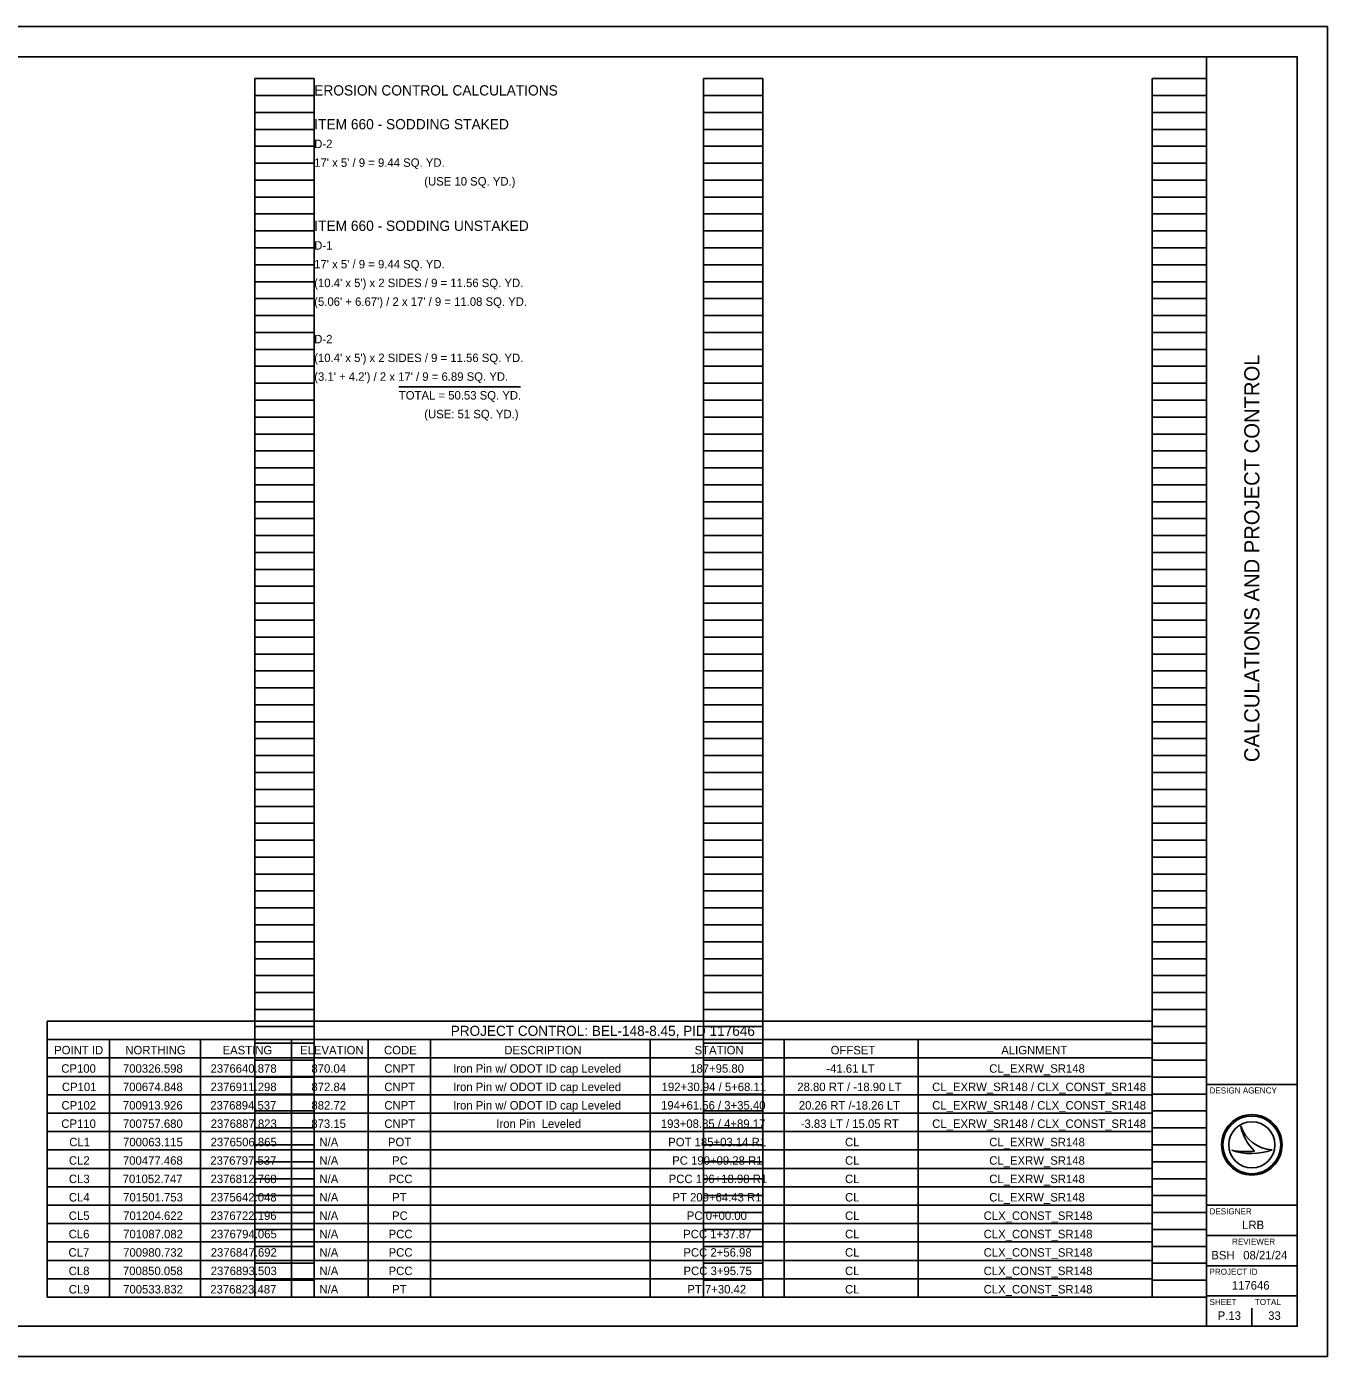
# Model space of a CAD drawing. Extents: x 0 to 34, y 0 to 22.
# Drawn here: x 12.48 to 34, y 0 to 22 of the extents above; entities that cross this region are included whole.
import ezdxf

# ---------------------------------------------------------------- set-up
doc = ezdxf.new("R2010")
doc.units = 0
for name, color, linetype in [('SH_Border', 7, 'Continuous'), ('SH_Cut_Line', 7, 'Continuous'), ('SH_Data', 7, 'Continuous'), ('SH_Text', 7, 'Continuous')]:
    doc.layers.add(name, color=color, linetype=linetype)

msp = doc.modelspace()

# ---------------------------------------------------------------- linework, layer by layer
at = {"layer": 'SH_Border'}
for p, q in [((32, 0.5), (32, 21.5)), ((32, 4.5), (33.5, 4.5)), ((32, 2.5), (33.5, 2.5)), ((32, 2), (33.5, 2)), ((32, 1.5), (33.5, 1.5)), ((32, 1), (33.5, 1))]:
    msp.add_line(p, q, dxfattribs=at)
msp.add_lwpolyline([(1.5, 21.5), (33.5, 21.5), (33.5, 0.5), (1.5, 0.5)], close=True, dxfattribs=at)
at = {"layer": 'SH_Cut_Line'}
msp.add_lwpolyline([(0, 0), (34, 0), (34, 22), (0, 22)], close=True, dxfattribs=at)
at = {"layer": 'SH_Data'}
for p, q in [((16.26, 0.98), (16.26, 21.14)), ((16.26, 21.14), (17.24, 21.14)), ((17.24, 0.98), (17.24, 21.14)), ((23.68, 0.98), (23.68, 21.14)), ((23.68, 21.14), (24.66, 21.14)), ((24.66, 0.98), (24.66, 21.14)), ((31.1, 0.98), (31.1, 21.14)), ((31.1, 21.14), (32, 21.14)), ((32, 0.98), (32, 21.14)), ((16.26, 20.86), (17.24, 20.86)), ((23.68, 20.86), (24.66, 20.86)), ((31.1, 20.86), (32, 20.86)), ((16.26, 20.58), (17.24, 20.58)), ((23.68, 20.58), (24.66, 20.58)), ((31.1, 20.58), (32, 20.58)), ((16.26, 20.3), (17.24, 20.3)), ((23.68, 20.3), (24.66, 20.3)), ((31.1, 20.3), (32, 20.3)), ((16.26, 20.02), (17.24, 20.02)), ((23.68, 20.02), (24.66, 20.02)), ((31.1, 20.02), (32, 20.02)), ((16.26, 19.74), (17.24, 19.74)), ((23.68, 19.74), (24.66, 19.74)), ((31.1, 19.74), (32, 19.74)), ((16.26, 19.46), (17.24, 19.46)), ((23.68, 19.46), (24.66, 19.46)), ((31.1, 19.46), (32, 19.46)), ((16.26, 19.18), (17.24, 19.18)), ((23.68, 19.18), (24.66, 19.18)), ((31.1, 19.18), (32, 19.18)), ((16.26, 18.9), (17.24, 18.9)), ((23.68, 18.9), (24.66, 18.9)), ((31.1, 18.9), (32, 18.9)), ((16.26, 18.62), (17.24, 18.62)), ((23.68, 18.62), (24.66, 18.62)), ((31.1, 18.62), (32, 18.62)), ((16.26, 18.34), (17.24, 18.34)), ((23.68, 18.34), (24.66, 18.34)), ((31.1, 18.34), (32, 18.34)), ((16.26, 18.06), (17.24, 18.06)), ((23.68, 18.06), (24.66, 18.06)), ((31.1, 18.06), (32, 18.06)), ((16.26, 17.78), (17.24, 17.78)), ((23.68, 17.78), (24.66, 17.78)), ((31.1, 17.78), (32, 17.78)), ((16.26, 17.5), (17.24, 17.5)), ((23.68, 17.5), (24.66, 17.5)), ((31.1, 17.5), (32, 17.5)), ((16.26, 17.22), (17.24, 17.22)), ((23.68, 17.22), (24.66, 17.22)), ((31.1, 17.22), (32, 17.22)), ((16.26, 16.94), (17.24, 16.94)), ((23.68, 16.94), (24.66, 16.94)), ((31.1, 16.94), (32, 16.94)), ((16.26, 16.66), (17.24, 16.66)), ((23.68, 16.66), (24.66, 16.66)), ((31.1, 16.66), (32, 16.66)), ((16.26, 16.38), (17.24, 16.38)), ((23.68, 16.38), (24.66, 16.38)), ((31.1, 16.38), (32, 16.38)), ((16.26, 16.1), (17.24, 16.1)), ((23.68, 16.1), (24.66, 16.1)), ((31.1, 16.1), (32, 16.1)), ((16.26, 15.82), (17.24, 15.82)), ((23.68, 15.82), (24.66, 15.82)), ((31.1, 15.82), (32, 15.82)), ((16.26, 15.54), (17.24, 15.54)), ((23.68, 15.54), (24.66, 15.54)), ((31.1, 15.54), (32, 15.54)), ((16.26, 15.26), (17.24, 15.26)), ((23.68, 15.26), (24.66, 15.26)), ((31.1, 15.26), (32, 15.26)), ((16.26, 14.98), (17.24, 14.98)), ((23.68, 14.98), (24.66, 14.98)), ((31.1, 14.98), (32, 14.98)), ((16.26, 14.7), (17.24, 14.7)), ((23.68, 14.7), (24.66, 14.7)), ((31.1, 14.7), (32, 14.7)), ((16.26, 14.42), (17.24, 14.42)), ((23.68, 14.42), (24.66, 14.42)), ((31.1, 14.42), (32, 14.42)), ((16.26, 14.14), (17.24, 14.14)), ((23.68, 14.14), (24.66, 14.14)), ((31.1, 14.14), (32, 14.14)), ((16.26, 13.86), (17.24, 13.86)), ((23.68, 13.86), (24.66, 13.86)), ((31.1, 13.86), (32, 13.86)), ((16.26, 13.58), (17.24, 13.58)), ((23.68, 13.58), (24.66, 13.58)), ((31.1, 13.58), (32, 13.58)), ((16.26, 13.3), (17.24, 13.3)), ((23.68, 13.3), (24.66, 13.3)), ((31.1, 13.3), (32, 13.3)), ((16.26, 13.02), (17.24, 13.02)), ((23.68, 13.02), (24.66, 13.02)), ((31.1, 13.02), (32, 13.02)), ((16.26, 12.74), (17.24, 12.74)), ((23.68, 12.74), (24.66, 12.74)), ((31.1, 12.74), (32, 12.74)), ((16.26, 12.46), (17.24, 12.46)), ((23.68, 12.46), (24.66, 12.46)), ((31.1, 12.46), (32, 12.46)), ((16.26, 12.18), (17.24, 12.18)), ((23.68, 12.18), (24.66, 12.18)), ((31.1, 12.18), (32, 12.18)), ((16.26, 11.9), (17.24, 11.9)), ((23.68, 11.9), (24.66, 11.9)), ((31.1, 11.9), (32, 11.9)), ((16.26, 11.62), (17.24, 11.62)), ((23.68, 11.62), (24.66, 11.62)), ((31.1, 11.62), (32, 11.62)), ((16.26, 11.34), (17.24, 11.34)), ((23.68, 11.34), (24.66, 11.34)), ((31.1, 11.34), (32, 11.34)), ((16.26, 11.06), (17.24, 11.06)), ((23.68, 11.06), (24.66, 11.06)), ((31.1, 11.06), (32, 11.06)), ((16.26, 10.78), (17.24, 10.78)), ((23.68, 10.78), (24.66, 10.78)), ((31.1, 10.78), (32, 10.78)), ((16.26, 10.5), (17.24, 10.5)), ((23.68, 10.5), (24.66, 10.5)), ((31.1, 10.5), (32, 10.5)), ((16.26, 10.22), (17.24, 10.22)), ((23.68, 10.22), (24.66, 10.22)), ((31.1, 10.22), (32, 10.22)), ((16.26, 9.94), (17.24, 9.94)), ((23.68, 9.94), (24.66, 9.94)), ((31.1, 9.94), (32, 9.94)), ((16.26, 9.66), (17.24, 9.66)), ((23.68, 9.66), (24.66, 9.66)), ((31.1, 9.66), (32, 9.66)), ((16.26, 9.38), (17.24, 9.38)), ((23.68, 9.38), (24.66, 9.38)), ((31.1, 9.38), (32, 9.38)), ((16.26, 9.1), (17.24, 9.1)), ((23.68, 9.1), (24.66, 9.1)), ((31.1, 9.1), (32, 9.1)), ((16.26, 8.82), (17.24, 8.82)), ((23.68, 8.82), (24.66, 8.82)), ((31.1, 8.82), (32, 8.82)), ((16.26, 8.54), (17.24, 8.54)), ((23.68, 8.54), (24.66, 8.54)), ((31.1, 8.54), (32, 8.54)), ((16.26, 8.26), (17.24, 8.26)), ((23.68, 8.26), (24.66, 8.26)), ((31.1, 8.26), (32, 8.26)), ((16.26, 7.98), (17.24, 7.98)), ((23.68, 7.98), (24.66, 7.98)), ((31.1, 7.98), (32, 7.98)), ((16.26, 7.7), (17.24, 7.7)), ((23.68, 7.7), (24.66, 7.7)), ((31.1, 7.7), (32, 7.7)), ((16.26, 7.42), (17.24, 7.42)), ((23.68, 7.42), (24.66, 7.42)), ((31.1, 7.42), (32, 7.42)), ((16.26, 7.14), (17.24, 7.14)), ((23.68, 7.14), (24.66, 7.14)), ((31.1, 7.14), (32, 7.14)), ((16.26, 6.86), (17.24, 6.86)), ((23.68, 6.86), (24.66, 6.86)), ((31.1, 6.86), (32, 6.86)), ((16.26, 6.58), (17.24, 6.58)), ((23.68, 6.58), (24.66, 6.58)), ((31.1, 6.58), (32, 6.58)), ((16.26, 6.3), (17.24, 6.3)), ((23.68, 6.3), (24.66, 6.3)), ((31.1, 6.3), (32, 6.3)), ((16.26, 6.02), (17.24, 6.02)), ((23.68, 6.02), (24.66, 6.02)), ((31.1, 6.02), (32, 6.02)), ((16.26, 5.74), (17.24, 5.74)), ((23.68, 5.74), (24.66, 5.74)), ((31.1, 5.74), (32, 5.74)), ((16.26, 5.46), (17.24, 5.46)), ((23.68, 5.46), (24.66, 5.46)), ((31.1, 5.46), (32, 5.46)), ((16.26, 5.18), (17.24, 5.18)), ((23.68, 5.18), (24.66, 5.18)), ((31.1, 5.18), (32, 5.18)), ((16.26, 4.9), (17.24, 4.9)), ((23.68, 4.9), (24.66, 4.9)), ((31.1, 4.9), (32, 4.9)), ((16.26, 4.62), (17.24, 4.62)), ((23.68, 4.62), (24.66, 4.62)), ((31.1, 4.62), (32, 4.62)), ((16.26, 4.34), (17.24, 4.34)), ((23.68, 4.34), (24.66, 4.34)), ((31.1, 4.34), (32, 4.34)), ((16.26, 4.06), (17.24, 4.06)), ((23.68, 4.06), (24.66, 4.06)), ((31.1, 4.06), (32, 4.06)), ((16.26, 3.78), (17.24, 3.78)), ((23.68, 3.78), (24.66, 3.78)), ((31.1, 3.78), (32, 3.78)), ((32.567, 3.81), (32.567, 3.81)), ((16.26, 3.5), (17.24, 3.5)), ((23.68, 3.5), (24.66, 3.5)), ((31.1, 3.5), (32, 3.5)), ((32.417, 3.41), (32.417, 3.41)), ((32.75, 3.5), (32.75, 3.5)), ((33.087, 3.419), (33.087, 3.419)), ((16.26, 3.22), (17.24, 3.22)), ((23.68, 3.22), (24.66, 3.22)), ((31.1, 3.22), (32, 3.22)), ((16.26, 2.94), (17.24, 2.94)), ((23.68, 2.94), (24.66, 2.94)), ((31.1, 2.94), (32, 2.94)), ((16.26, 2.66), (17.24, 2.66)), ((23.68, 2.66), (24.66, 2.66)), ((31.1, 2.66), (32, 2.66)), ((16.26, 2.38), (17.24, 2.38)), ((23.68, 2.38), (24.66, 2.38)), ((31.1, 2.38), (32, 2.38)), ((16.26, 2.1), (17.24, 2.1)), ((23.68, 2.1), (24.66, 2.1)), ((31.1, 2.1), (32, 2.1)), ((16.26, 1.82), (17.24, 1.82)), ((23.68, 1.82), (24.66, 1.82)), ((31.1, 1.82), (32, 1.82)), ((16.26, 1.54), (17.24, 1.54)), ((23.68, 1.54), (24.66, 1.54)), ((31.1, 1.54), (32, 1.54)), ((16.26, 1.26), (17.24, 1.26)), ((23.68, 1.26), (24.66, 1.26)), ((31.1, 1.26), (32, 1.26)), ((16.26, 0.98), (17.24, 0.98)), ((23.68, 0.98), (24.66, 0.98)), ((31.1, 0.98), (32, 0.98)), ((32.375, 0.675), (32.375, 0.675)), ((32.75, 0.5), (32.75, 0.8))]:
    msp.add_line(p, q, dxfattribs=at)
for radius in [0.5, 0.477, 0.477, 0.382]:
    msp.add_circle((32.75, 3.5), radius, dxfattribs=at)
for centre, radius, start, end in [((33.116, 3.998), 0.58, 198.9257, 198.9319), ((33.347, 3.97), 0.796, 191.6379, 191.6421), ((33.116, 3.998), 0.58, 198.9319, 267.1657), ((33.347, 3.97), 0.796, 191.6421, 226.0947), ((32.739, 4.37), 1.013, 251.4576, 290.0832), ((32.648, 4.654), 1.266, 259.4964, 259.4995), ((32.739, 4.37), 1.013, 251.4527, 251.4576), ((32.648, 4.654), 1.266, 259.4995, 276.6672)]:
    msp.add_arc(centre, radius, start, end, dxfattribs=at)
at = {"layer": 'SH_Text'}
for p, q in [((18.64, 16.039), (20.655, 16.039)), ((12.822, 5.545), (31.1, 5.545)), ((12.822, 5.545), (12.822, 0.98)), ((31.1, 5.545), (31.1, 0.98)), ((12.822, 5.241), (31.1, 5.241)), ((13.854, 5.241), (13.854, 4.937)), ((15.358, 5.241), (15.358, 4.937)), ((16.863, 5.241), (16.863, 4.937)), ((18.131, 5.241), (18.131, 4.937)), ((19.163, 5.241), (19.163, 4.937)), ((22.798, 5.241), (22.798, 4.937)), ((25.013, 5.241), (25.013, 4.937)), ((27.228, 5.241), (27.228, 4.937)), ((12.822, 4.937), (31.1, 4.937)), ((13.854, 4.937), (13.854, 0.98)), ((15.358, 4.937), (15.358, 0.98)), ((16.863, 4.937), (16.863, 0.98)), ((18.131, 4.937), (18.131, 0.98)), ((19.163, 4.937), (19.163, 0.98)), ((22.798, 4.937), (22.798, 0.98)), ((25.013, 4.937), (25.013, 0.98)), ((27.228, 4.937), (27.228, 0.98)), ((12.822, 4.632), (31.1, 4.632)), ((12.822, 4.328), (31.1, 4.328)), ((12.822, 4.023), (31.1, 4.023)), ((12.822, 3.719), (31.1, 3.719)), ((12.822, 3.415), (31.1, 3.415)), ((12.822, 3.11), (31.1, 3.11)), ((12.822, 2.806), (31.1, 2.806)), ((12.822, 2.502), (31.1, 2.502)), ((12.822, 2.197), (31.1, 2.197)), ((12.822, 1.893), (31.1, 1.893)), ((12.822, 1.589), (31.1, 1.589)), ((12.822, 1.284), (31.1, 1.284)), ((12.822, 0.98), (31.1, 0.98))]:
    msp.add_line(p, q, dxfattribs=at)

# ---------------------------------------------------------------- texts
at = {"layer": 'SH_Data'}
msp.add_text('CALCULATIONS AND PROJECT CONTROL', height=0.25, rotation=90, dxfattribs=at).set_placement((32.875, 9.832))
for s, height, p in [('DESIGN AGENCY', 0.1, (32.05, 4.35)), ('DESIGNER', 0.1, (32.05, 2.35)), ('LRB', 0.14, (32.589, 2.105)), ('REVIEWER', 0.1, (32.422, 1.85)), ('BSH', 0.14, (32.08, 1.605)), ('08/21/24', 0.14, (32.608, 1.605)), ('PROJECT ID', 0.1, (32.05, 1.35)), ('117646', 0.14, (32.419, 1.105)), ('SHEET', 0.1, (32.05, 0.85)), ('TOTAL', 0.1, (32.8, 0.85)), ('P.13', 0.14, (32.185, 0.605)), ('33', 0.14, (33.02, 0.605))]:
    msp.add_text(s, height=height, dxfattribs=at).set_placement(p)
at = {"layer": 'SH_Text'}
for s, height, p in [('EROSION CONTROL CALCULATIONS', 0.17, (17.24, 20.86)), ('ITEM 660 - SODDING STAKED', 0.17, (17.24, 20.3)), ('D-2', 0.14, (17.24, 19.99)), ("17' x 5' / 9 = 9.44 SQ. YD.", 0.14, (17.24, 19.68)), ('(USE 10 SQ. YD.)', 0.14, (19.06, 19.37)), ('ITEM 660 - SODDING UNSTAKED', 0.17, (17.24, 18.62)), ('D-1', 0.14, (17.24, 18.31)), ("17' x 5' / 9 = 9.44 SQ. YD. ", 0.14, (17.24, 18)), ("(10.4' x 5') x 2 SIDES / 9 = 11.56 SQ. YD. ", 0.14, (17.24, 17.69)), ("(5.06' + 6.67') / 2 x 17' / 9 = 11.08 SQ. YD. ", 0.14, (17.24, 17.38)), ('D-2 ', 0.14, (17.24, 16.76)), ("(10.4' x 5') x 2 SIDES / 9 = 11.56 SQ. YD. ", 0.14, (17.24, 16.45)), ("(3.1' + 4.2') / 2 x 17' / 9 = 6.89 SQ. YD. ", 0.14, (17.24, 16.14)), ('TOTAL = 50.53 SQ. YD. ', 0.14, (18.64, 15.83)), ('(USE: 51 SQ. YD.)', 0.14, (19.06, 15.52)), ('PROJECT CONTROL: BEL-148-8.45, PID 117646', 0.168, (19.498, 5.302)), ('POINT ID', 0.14, (12.938, 4.997)), ('NORTHING', 0.14, (14.115, 4.997)), ('EASTING', 0.14, (15.724, 4.997)), ('ELEVATION', 0.14, (17.006, 4.997)), ('CODE', 0.14, (18.395, 4.997)), ('DESCRIPTION', 0.14, (20.384, 4.997)), ('STATION', 0.14, (23.532, 4.997)), ('OFFSET', 0.14, (25.783, 4.997)), ('ALIGNMENT', 0.14, (28.605, 4.997)), ('Iron Pin w/ ODOT ID cap Leveled', 0.14, (19.538, 4.693)), ('CP100', 0.14, (13.056, 4.693)), ('700326.598', 0.14, (14.076, 4.693)), ('2376640.878', 0.14, (15.525, 4.693)), ('870.04', 0.14, (17.194, 4.693)), ('CNPT', 0.14, (18.4, 4.693)), (' 187+95.80', 0.14, (23.407, 4.693)), ('-41.61 LT', 0.14, (25.711, 4.693)), ('CL_EXRW_SR148', 0.14, (28.406, 4.693)), ('CP101', 0.14, (13.066, 4.389)), ('700674.848', 0.14, (14.076, 4.389)), ('2376911.298', 0.14, (15.525, 4.389)), ('872.84', 0.14, (17.194, 4.389)), ('CNPT', 0.14, (18.4, 4.389)), ('Iron Pin w/ ODOT ID cap Leveled', 0.14, (19.538, 4.389)), ('192+30.94 / 5+68.11', 0.14, (22.987, 4.389)), ('28.80 RT / -18.90 LT', 0.14, (25.231, 4.389)), ('CL_EXRW_SR148 / CLX_CONST_SR148', 0.14, (27.462, 4.389)), ('CP102', 0.14, (13.059, 4.084)), ('700913.926', 0.14, (14.075, 4.084)), ('2376894.537', 0.14, (15.521, 4.084)), ('882.72', 0.14, (17.194, 4.084)), ('CNPT', 0.14, (18.4, 4.084)), ('Iron Pin w/ ODOT ID cap Leveled', 0.14, (19.538, 4.084)), ('194+61.56 / 3+35.40', 0.14, (22.977, 4.084)), ('20.26 RT /-18.26 LT', 0.14, (25.256, 4.084)), ('CL_EXRW_SR148 / CLX_CONST_SR148', 0.14, (27.462, 4.084)), ('CP110', 0.14, (13.056, 3.78)), ('700757.680', 0.14, (14.076, 3.78)), ('2376887.823', 0.14, (15.528, 3.78)), ('873.15', 0.14, (17.192, 3.78)), ('CNPT', 0.14, (18.4, 3.78)), ('Iron Pin  Leveled', 0.14, (20.252, 3.78)), ('193+08.85 / 4+89.17', 0.14, (22.974, 3.78)), ('-3.83 LT / 15.05 RT', 0.14, (25.287, 3.78)), ('CL_EXRW_SR148 / CLX_CONST_SR148', 0.14, (27.462, 3.78)), ('CL1', 0.14, (13.188, 3.476)), ('700063.115', 0.14, (14.078, 3.476)), ('2376506.865', 0.14, (15.527, 3.476)), ('N/A', 0.14, (17.326, 3.476)), ('POT', 0.14, (18.459, 3.476)), ('POT 185+03.14 R1', 0.14, (23.096, 3.476)), ('CL', 0.14, (26.021, 3.476)), ('CL_EXRW_SR148', 0.14, (28.406, 3.476)), ('CL2', 0.14, (13.182, 3.171)), ('700477.468', 0.14, (14.076, 3.171)), ('2376797.537', 0.14, (15.521, 3.171)), ('N/A', 0.14, (17.326, 3.171)), ('PC', 0.14, (18.528, 3.171)), ('PC 190+09.28 R1', 0.14, (23.162, 3.171)), ('CL', 0.14, (26.021, 3.171)), ('CL_EXRW_SR148', 0.14, (28.406, 3.171)), ('CL3', 0.14, (13.182, 2.867)), ('701052.747', 0.14, (14.072, 2.867)), ('2376812.768', 0.14, (15.525, 2.867)), ('N/A', 0.14, (17.326, 2.867)), ('PCC', 0.14, (18.471, 2.867)), ('PCC 196+18.98 R1', 0.14, (23.104, 2.867)), ('CL', 0.14, (26.021, 2.867)), ('CL_EXRW_SR148', 0.14, (28.406, 2.867)), ('CL4', 0.14, (13.182, 2.563)), ('701501.753', 0.14, (14.079, 2.563)), ('2375642.048', 0.14, (15.525, 2.563)), ('N/A', 0.14, (17.326, 2.563)), ('PT', 0.14, (18.529, 2.563)), ('PT 209+64.43 R1', 0.14, (23.166, 2.563)), ('CL', 0.14, (26.021, 2.563)), ('CL_EXRW_SR148', 0.14, (28.406, 2.563)), ('CL5', 0.14, (13.18, 2.258)), ('701204.622', 0.14, (14.079, 2.258)), ('2376722.196', 0.14, (15.524, 2.258)), ('N/A', 0.14, (17.326, 2.258)), ('PC', 0.14, (18.528, 2.258)), ('PC 0+00.00', 0.14, (23.404, 2.258)), ('CL', 0.14, (26.021, 2.258)), ('CLX_CONST_SR148', 0.14, (28.314, 2.258)), ('CL6', 0.14, (13.178, 1.954)), ('701087.082', 0.14, (14.079, 1.954)), ('2376794.065', 0.14, (15.527, 1.954)), ('N/A', 0.14, (17.326, 1.954)), ('PCC', 0.14, (18.471, 1.954)), ('PCC 1+37.87', 0.14, (23.343, 1.954)), ('CL', 0.14, (26.021, 1.954)), ('CLX_CONST_SR148', 0.14, (28.314, 1.954)), ('CL7', 0.14, (13.175, 1.65)), ('700980.732', 0.14, (14.079, 1.65)), ('2376847.692', 0.14, (15.528, 1.65)), ('N/A', 0.14, (17.326, 1.65)), ('PCC', 0.14, (18.471, 1.65)), ('PCC 2+56.98', 0.14, (23.347, 1.65)), ('CL', 0.14, (26.021, 1.65)), ('CLX_CONST_SR148', 0.14, (28.314, 1.65)), ('CL8', 0.14, (13.179, 1.345)), ('700850.058', 0.14, (14.076, 1.345)), ('2376893.503', 0.14, (15.528, 1.345)), ('N/A', 0.14, (17.326, 1.345)), ('PCC', 0.14, (18.471, 1.345)), ('PCC 3+95.75', 0.14, (23.349, 1.345)), ('CL', 0.14, (26.021, 1.345)), ('CLX_CONST_SR148', 0.14, (28.314, 1.345)), ('CL9', 0.14, (13.18, 1.041)), ('700533.832', 0.14, (14.079, 1.041)), ('2376823.487', 0.14, (15.521, 1.041)), ('N/A', 0.14, (17.326, 1.041)), ('PT', 0.14, (18.529, 1.041)), ('PT 7+30.42', 0.14, (23.412, 1.041)), ('CL', 0.14, (26.021, 1.041)), ('CLX_CONST_SR148', 0.14, (28.314, 1.041))]:
    msp.add_text(s, height=height, dxfattribs=at).set_placement(p)

doc.saveas('drawing.dxf')
